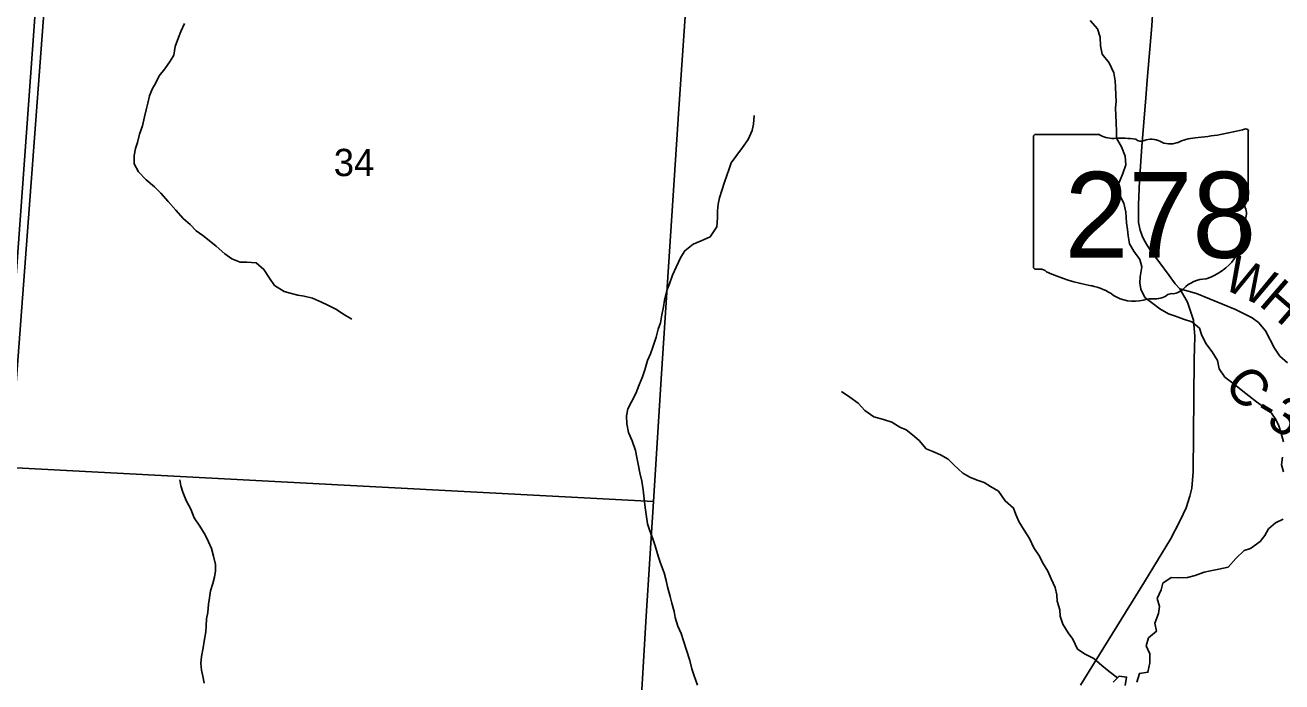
# Model space of a CAD drawing. Extents: x 0 to 34, y 0 to 22.
# Drawn here: x 5.215 to 7.144, y 15.589 to 16.597 of the extents above; entities that cross this region are included whole.
import ezdxf

# ---------------------------------------------------------------- set-up
doc = ezdxf.new("R2010")
doc.units = 0
for name, color, linetype in [('GM_X_County_Road', 7, 'Continuous'), ('GM_X_County_Road_Text', 7, 'Continuous'), ('GM_X_Minor_River', 7, 'Continuous'), ('GM_X_Section', 7, 'Continuous'), ('GM_X_Section_Text', 7, 'Continuous'), ('GM_X_State_Location', 7, 'Continuous'), ('GM_X_State_Route', 7, 'Continuous'), ('GM_X_State_Shield', 7, 'Continuous'), ('SC_Scratch1', 7, 'Continuous')]:
    doc.layers.add(name, color=color, linetype=linetype)

msp = doc.modelspace()

# ---------------------------------------------------------------- linework, layer by layer
at = {"layer": 'GM_X_County_Road'}
msp.add_lwpolyline([(6.9871, 16.1919), (7.0129, 16.1849), (7.0725, 16.1602), (7.098, 16.1477), (7.1076, 16.1404), (7.1188, 16.1274), (7.1323, 16.1009), (7.1404, 16.0889), (7.1524, 16.0787)], dxfattribs=at)
at = {"layer": 'GM_X_Minor_River'}
for points in [[(5.4594, 16.5993), (5.4538, 16.5871), (5.45, 16.5776), (5.4451, 16.564), (5.4429, 16.5507), (5.4373, 16.5412), (5.429, 16.5298), (5.4207, 16.5188), (5.4154, 16.5081), (5.4098, 16.4983), (5.4056, 16.4884), (5.403, 16.477), (5.4008, 16.4668), (5.3982, 16.4561), (5.3948, 16.4421), (5.3903, 16.4296), (5.3873, 16.4167), (5.3843, 16.4072), (5.3821, 16.3969), (5.3821, 16.3837), (5.3886, 16.3716), (5.4008, 16.3595), (5.4133, 16.3485), (5.4232, 16.339), (5.4342, 16.3262), (5.446, 16.3129), (5.4574, 16.3001), (5.468, 16.291), (5.4771, 16.2811), (5.4877, 16.274), (5.4972, 16.2664), (5.5078, 16.2573), (5.5215, 16.246), (5.5321, 16.238), (5.545, 16.2328), (5.5549, 16.2332), (5.5696, 16.2321), (5.5814, 16.2219), (5.5898, 16.2086), (5.5974, 16.1973), (5.6122, 16.1882), (5.6216, 16.1852), (5.6334, 16.1826), (5.6432, 16.1807), (5.6561, 16.1777), (5.6698, 16.1716), (5.6796, 16.1671), (5.6925, 16.1603), (5.7024, 16.1539), (5.716, 16.1456)], [(6.8494, 16.6038), (6.8608, 16.5909), (6.8646, 16.578), (6.8654, 16.5648), (6.8677, 16.5523), (6.8788, 16.539), (6.886, 16.5235), (6.8879, 16.5114), (6.8883, 16.5019), (6.8888, 16.489), (6.8892, 16.4795), (6.8884, 16.47), (6.8889, 16.4579), (6.8893, 16.4473), (6.8897, 16.4329), (6.8897, 16.4234), (6.8977, 16.4101), (6.9031, 16.3954), (6.9042, 16.3825), (6.8997, 16.3692), (6.8949, 16.3578), (6.8904, 16.3476), (6.8934, 16.3381), (6.901, 16.3233), (6.9041, 16.3097), (6.9053, 16.2934), (6.9065, 16.2831), (6.9076, 16.2733), (6.9099, 16.2611), (6.9164, 16.2498), (6.9255, 16.2373), (6.929, 16.2259), (6.9264, 16.2107), (6.9257, 16.2013), (6.9272, 16.1918), (6.9333, 16.1789), (6.9458, 16.1695), (6.9564, 16.1615)], [(6.247, 15.5838), (6.2417, 15.5985), (6.2383, 15.6092), (6.2352, 15.622), (6.2298, 15.6376), (6.2253, 15.652), (6.2218, 15.663), (6.2165, 15.6743), (6.2126, 15.6876), (6.2111, 15.6971), (6.2076, 15.71), (6.2046, 15.7202), (6.2008, 15.735), (6.1988, 15.7444), (6.1958, 15.7562), (6.19, 15.771), (6.187, 15.7804), (6.182, 15.7979), (6.1782, 15.8085), (6.1732, 15.8221), (6.1702, 15.8316), (6.1678, 15.846), (6.1663, 15.8566), (6.1651, 15.8699), (6.1636, 15.8839), (6.1612, 15.8968), (6.1582, 15.9097), (6.1562, 15.9203), (6.1539, 15.9332), (6.1516, 15.9438), (6.1463, 15.9589), (6.1409, 15.9718), (6.1382, 15.9847), (6.1378, 15.9972), (6.1397, 16.0078), (6.1453, 16.0189), (6.1521, 16.0314), (6.1574, 16.0447), (6.1622, 16.0568), (6.166, 16.0678), (6.1701, 16.0819), (6.1746, 16.0925), (6.178, 16.1024), (6.1832, 16.1179), (6.1866, 16.1304), (6.19, 16.1399), (6.1922, 16.1521), (6.1944, 16.1646), (6.1963, 16.1748), (6.1997, 16.1896), (6.2038, 16.1995), (6.2083, 16.2128), (6.2139, 16.2253), (6.2214, 16.2409), (6.2275, 16.2504), (6.2399, 16.2606), (6.2524, 16.2656), (6.2664, 16.2721), (6.2762, 16.2873), (6.2776, 16.3009), (6.2776, 16.3115), (6.2787, 16.3222), (6.2806, 16.3316), (6.2843, 16.3427), (6.2881, 16.3556), (6.2918, 16.3662), (6.2952, 16.3761), (6.2986, 16.3855), (6.3054, 16.395), (6.3159, 16.4091), (6.3246, 16.4212), (6.3306, 16.4349), (6.3328, 16.4448), (6.3335, 16.4581)], [(6.9564, 16.1615), (6.9697, 16.1536), (6.9803, 16.1502), (6.9928, 16.1457), (7.0057, 16.1415), (7.0175, 16.1317), (7.0205, 16.1219), (7.027, 16.1082), (7.0369, 16.0954), (7.0449, 16.0821), (7.0472, 16.0692), (7.0563, 16.0563), (7.0704, 16.0458), (7.0837, 16.0348), (7.0932, 16.028), (7.1049, 16.0185), (7.1174, 16.0095), (7.1277, 16.0015), (7.1342, 15.9917), (7.1391, 15.9818), (7.1422, 15.972), (7.1464, 15.9572)], [(6.8914, 15.5953), (6.8788, 15.605), (6.8674, 15.6141), (6.8549, 15.6247), (6.842, 15.6315), (6.8298, 15.6394), (6.8226, 15.6546), (6.8157, 15.6644), (6.8077, 15.6777), (6.8035, 15.6898), (6.8027, 15.6997), (6.7989, 15.7129), (6.7981, 15.7224), (6.7958, 15.7338), (6.7897, 15.747), (6.7844, 15.7591), (6.7764, 15.772), (6.7718, 15.7819), (6.7631, 15.7947), (6.7562, 15.8091), (6.7482, 15.822), (6.7398, 15.8349), (6.7356, 15.8459), (6.7318, 15.8557), (6.7189, 15.8667), (6.7087, 15.8814), (6.6965, 15.8886), (6.6867, 15.895), (6.676, 15.8984), (6.6647, 15.9029), (6.6541, 15.909), (6.6408, 15.9215), (6.6313, 15.9305), (6.6195, 15.9373), (6.6078, 15.9426), (6.5979, 15.9468), (6.5869, 15.9593), (6.577, 15.968), (6.5668, 15.9755), (6.5573, 15.98), (6.5452, 15.9876), (6.5323, 15.9917), (6.5175, 15.9955), (6.5035, 16.0053), (6.4932, 16.0167), (6.4807, 16.0257), (6.4678, 16.0344)], [(7.1446, 15.9337), (7.1431, 15.9219), (7.1461, 15.9113)], [(5.4896, 15.5872), (5.4877, 15.5975), (5.4854, 15.6069), (5.4846, 15.6172), (5.4857, 15.6278), (5.4879, 15.6411), (5.4894, 15.6517), (5.4924, 15.6657), (5.4927, 15.6752), (5.4934, 15.6858), (5.4953, 15.6953), (5.4964, 15.7082), (5.4979, 15.7181), (5.4993, 15.7287), (5.5027, 15.7397), (5.5053, 15.7499), (5.5072, 15.7594), (5.5068, 15.7689), (5.5041, 15.7818), (5.5006, 15.7935), (5.4964, 15.8038), (5.4911, 15.8144), (5.4827, 15.828), (5.4744, 15.8409), (5.469, 15.8538), (5.4622, 15.8674), (5.4568, 15.8803), (5.4538, 15.8897), (5.4522, 15.8992)], [(7.1456, 15.8385), (7.1339, 15.8328), (7.1233, 15.8237), (7.1177, 15.8138), (7.1102, 15.8043), (7.0954, 15.7937), (7.0856, 15.7906), (7.0728, 15.7781), (7.0611, 15.7651), (7.0467, 15.7617), (7.0342, 15.7594), (7.0244, 15.7571), (7.0108, 15.7521), (6.9987, 15.749), (6.985, 15.7486), (6.9737, 15.749), (6.9612, 15.7402), (6.9586, 15.7304), (6.9522, 15.7171), (6.9557, 15.7046), (6.9542, 15.694), (6.9486, 15.6792), (6.9512, 15.6666), (6.9388, 15.6564), (6.9354, 15.6442), (6.9408, 15.6321), (6.9412, 15.6181), (6.9382, 15.6037), (6.925, 15.6021), (6.9212, 15.5888)], [(6.9034, 15.5835), (6.9053, 15.5964), (6.8939, 15.5979), (6.8849, 15.5884)]]:
    msp.add_lwpolyline(points, dxfattribs=at)
at = {"layer": 'GM_X_Section'}
for points in [[(4.2561, 17.0047), (5.2673, 16.9365), (5.1915, 15.9177), (4.189, 15.9719)], [(6.2455, 16.872), (6.2183, 16.4683), (6.1917, 16.0616), (6.1792, 15.8658), (5.1915, 15.9177), (5.2673, 16.9365)], [(5.1915, 15.9177), (6.1792, 15.8658), (6.168, 15.6897), (6.1161, 14.8127), (5.117, 14.8733)]]:
    msp.add_lwpolyline(points, close=True, dxfattribs=at)
at = {"layer": 'GM_X_State_Route'}
msp.add_lwpolyline([(6.8346, 15.5838), (6.933, 15.7423), (6.9728, 15.8078), (6.9876, 15.8367), (6.9967, 15.8562), (7.0025, 15.8739), (7.0056, 15.8862), (7.0074, 15.9112), (7.0092, 16.0837), (7.0103, 16.1191), (7.0079, 16.1441), (6.9986, 16.1714), (6.9871, 16.1919), (6.98, 16.1998), (6.9709, 16.2125), (6.9546, 16.234), (6.9443, 16.2478), (6.9373, 16.2581), (6.9325, 16.2668), (6.9293, 16.2733), (6.9261, 16.2822), (6.9236, 16.2938), (6.9234, 16.3031), (6.9236, 16.3215), (6.9253, 16.3576), (6.9287, 16.4104), (6.9348, 16.485), (6.9369, 16.5124), (6.9441, 16.5957), (6.9458, 16.621)], dxfattribs=at)
at = {"layer": 'GM_X_State_Shield'}
for p, q in [((7.0922, 16.3294), (7.0922, 16.4341)), ((6.7626, 16.4257), (6.7626, 16.2256)), ((6.8624, 16.4291), (6.7659, 16.4291)), ((7.0922, 16.3294), (7.0922, 16.3294))]:
    msp.add_line(p, q, dxfattribs=at)
for centre, major_axis, start_param, end_param in [((6.9748, 16.702), (0.3495, 0), 4.814394, 5.042369), ((7.0886, 16.4345), (0.00367, 0), 6.141152, 7.989035), ((6.7664, 16.4261), (0.00382, 0), 1.712693, 3.28349), ((6.8854, 16.4524), (0.037, 0), 4.042523, 4.731795), ((6.8977, 16.3168), (0.133, 0), 1.404758, 1.657858), ((6.9278, 16.4272), (0.0107, 0), 3.836095, 5.185415), ((6.9435, 16.404), (0.0222, 0), 0.950623, 2.079405), ((6.9722, 16.4358), (0.0267, 0), 4.081561, 5.145723), ((7.0194, 16.368), (0.0703, 0), 1.699011, 2.107814), ((7.0914, 16.3217), (0.00568, 0), 1.883978, 3.671073), ((7.0552, 16.3085), (0.0341, 0), 5.934695, 6.695948), ((7.0883, 16.329), (0.00393, 0), 5.05454, 6.418171), ((7.1054, 16.2856), (0.0248, 0), 2.387724, 3.262537), ((6.9944, 16.2723), (0.0874, 0), 5.101752, 6.440018), ((6.7664, 16.2251), (0.00385, 0), 3.00124, 4.508301), ((6.767, 16.2456), (0.0294, 0), 4.665946, 4.897461), ((6.773, 16.214), (0.0106, 0), 0.519207, 1.627899), ((6.9069, 16.3938), (0.2524, 0), 4.195997, 4.488961), ((7.0312, 16.1694), (0.0479, 0), 1.647645, 2.488434), ((6.8316, 16.1357), (0.079, 0), 0.823519, 1.323587), ((6.9738, 16.1787), (0.00752, 0), 1.147584, 2.315152), ((6.9706, 16.2062), (0.0282, 0), 4.937069, 5.64225), ((6.917, 16.213), (0.0501, 0), 4.026481, 4.996735), ((6.946, 16.1439), (0.0412, 0), 1.495662, 1.94098), ((6.9496, 16.1981), (0.0267, 0), 4.691044, 5.507374)]:
    msp.add_ellipse(centre, major_axis=major_axis, ratio=0.8, start_param=start_param, end_param=end_param, dxfattribs=at)
at = {"layer": 'SC_Scratch1'}
for points in [[(2.1, 19.1982), (2.1, 14.1), (5.0535, 14.1), (5.0814, 14.5016), (5.1049, 14.8414), (5.1794, 15.9156), (5.2761, 17.2534), (5.2869, 17.4026), (5.3506, 18.2846), (5.3662, 18.4999), (5.4007, 18.9779), (5.182, 18.9932), (4.7997, 19.0196), (4.7394, 19.0241), (4.3628, 19.0495), (3.3448, 19.1146), (2.3572, 19.1804)], [(5.0535, 14.1), (8.9, 14.1), (8.9, 18.7389), (8.2061, 18.7863), (7.2159, 18.8539), (6.8273, 18.8804), (5.9889, 18.9377), (5.4885, 18.9719), (5.4007, 18.9779), (5.3662, 18.4999), (5.3506, 18.2846), (5.2869, 17.4026), (5.2761, 17.2534), (5.1794, 15.9156), (5.1049, 14.8414), (5.0814, 14.5016)]]:
    msp.add_lwpolyline(points, close=True, dxfattribs=at)

# ---------------------------------------------------------------- texts
at = {"layer": 'GM_X_County_Road_Text'}
for s, rotation, p in [('W', 334.8852, (7.0503, 16.194)), ('H', 319.1869, (7.1065, 16.1683)), ('C', 311.0475, (7.0529, 16.0436)), ('-', 328.917, (7.0983, 15.996)), ('3', 327.2842, (7.1179, 15.9842))]:
    msp.add_text(s, height=0.0568, rotation=rotation, dxfattribs=at).set_placement(p)
at = {"layer": 'GM_X_Section_Text'}
msp.add_text('34', height=0.04186, rotation=0, dxfattribs=at).set_placement((5.6885, 16.365))
at = {"layer": 'GM_X_State_Location'}
for s in ['s', 'r']:
    msp.add_text(s, height=0.000189, dxfattribs=at).set_placement((6.9237, 16.3123))
msp.add_text('278', height=0.000189, rotation=0, dxfattribs=at).set_placement((6.8569, 16.2986))
at = {"layer": 'GM_X_State_Shield'}
msp.add_text('278', height=0.13184, dxfattribs=at).set_placement((6.8102, 16.2397))

doc.saveas('drawing.dxf')
